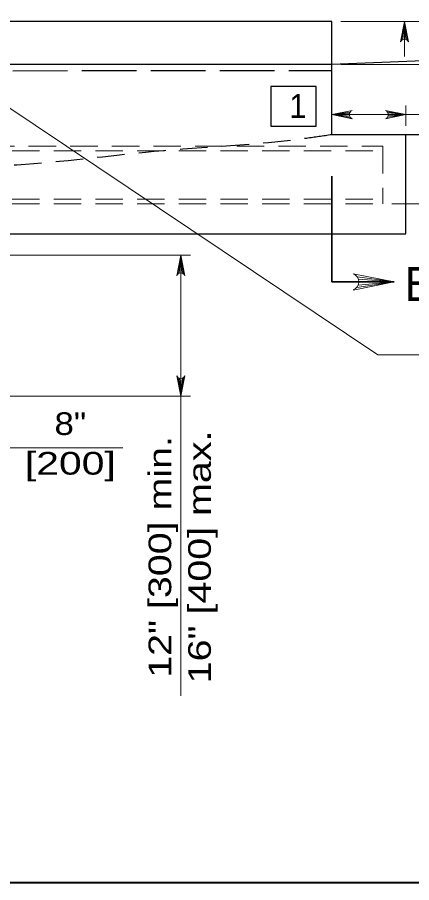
# Model space of a CAD drawing. Extents: x -1431.2 to -1397.2, y -1045.1 to -1001.1.
# Drawn here: x -1417.19 to -1414.42, y -1022.58 to -1016.52 of the extents above; entities that cross this region are included whole.
import ezdxf
from ezdxf.enums import TextEntityAlignment as Align

# ---------------------------------------------------------------- set-up
doc = ezdxf.new("R2010")
doc.units = 0
doc.header["$LTSCALE"] = 0.064
doc.linetypes.add('LONG_DASHED', pattern=[7.5, 6, -1.5])
doc.linetypes.add('MEDIUM_DASHED', pattern=[4.5, 3, -1.5])
doc.layers.add('1', color=7, linetype='Continuous', lineweight=13)

msp = doc.modelspace()

# ---------------------------------------------------------------- linework, layer by layer
at = {"layer": '1'}
for p, q in [((-1414.922, -1016.54658), (-1413.9755, -1016.54658)), ((-1414.49525, -1016.6775), (-1414.47525, -1016.54658)), ((-1414.48683, -1016.67258), (-1414.47525, -1016.54658)), ((-1414.47525, -1016.79125), (-1414.47525, -1016.54658)), ((-1414.47525, -1016.67025), (-1414.47525, -1016.54658)), ((-1414.46608, -1016.67158), (-1414.47525, -1016.54658)), ((-1414.45717, -1016.676), (-1414.47525, -1016.54658)), ((-1414.922, -1016.84758), (-1411.48458, -1016.84758)), ((-1414.59558, -1017.17883), (-1414.46475, -1017.19883)), ((-1414.46475, -1017.27683), (-1414.46475, -1017.13575)), ((-1414.85567, -1017.18067), (-1414.98508, -1017.19883)), ((-1414.86008, -1017.18967), (-1414.98508, -1017.19883)), ((-1414.98508, -1017.19883), (-1413.19358, -1017.19883)), ((-1414.86142, -1017.19883), (-1414.98508, -1017.19883)), ((-1414.85908, -1017.21042), (-1414.98508, -1017.19883)), ((-1414.85417, -1017.21883), (-1414.98508, -1017.19883)), ((-1414.59408, -1017.21692), (-1414.46475, -1017.19883)), ((-1414.59067, -1017.18717), (-1414.46475, -1017.19883)), ((-1414.58967, -1017.20792), (-1414.46475, -1017.19883)), ((-1414.58833, -1017.19883), (-1414.46475, -1017.19883)), ((-1414.922, -1017.33992), (-1412.21383, -1017.33992)), ((-1414.563, -1017.824), (-1412.22208, -1017.824)), ((-1417.76217, -1018.18442), (-1415.97617, -1018.18442)), ((-1416.0635, -1018.31525), (-1416.0435, -1018.18442)), ((-1416.05508, -1018.31033), (-1416.0435, -1018.18442)), ((-1416.0435, -1021.27142), (-1416.0435, -1018.18442)), ((-1416.0435, -1018.308), (-1416.0435, -1018.18442)), ((-1416.03433, -1018.30933), (-1416.0435, -1018.18442)), ((-1416.02542, -1018.31375), (-1416.0435, -1018.18442)), ((-1414.81025, -1018.4105), (-1414.54842, -1018.3705)), ((-1414.80717, -1018.33425), (-1414.54842, -1018.3705)), ((-1414.80033, -1018.39375), (-1414.54842, -1018.3705)), ((-1414.79842, -1018.35217), (-1414.54842, -1018.3705)), ((-1414.79575, -1018.3705), (-1414.54842, -1018.3705)), ((-1416.06158, -1019.0415), (-1416.0435, -1019.17083)), ((-1416.05267, -1019.04592), (-1416.0435, -1019.17083)), ((-1416.0235, -1019.04), (-1416.0435, -1019.17083)), ((-1416.03192, -1019.04492), (-1416.0435, -1019.17083)), ((-1416.0435, -1019.04725), (-1416.0435, -1019.17083)), ((-1417.775, -1019.17083), (-1415.97617, -1019.17083)), ((-1417.79208, -1019.53367), (-1416.45075, -1019.53367))]:
    msp.add_line(p, q, dxfattribs=at)
at = {"layer": '1', "lineweight": 25}
for p, q in [((-1411.525, -1016.71175), (-1414.98508, -1016.84758)), ((-1414.98508, -1016.84758), (-1417.70592, -1016.84758)), ((-1414.46475, -1018.03408), (-1414.46475, -1017.33992)), ((-1417.26308, -1018.03408), (-1414.46475, -1018.03408))]:
    msp.add_line(p, q, dxfattribs=at)
at = {"layer": '1', "linetype": 'LONG_DASHED', "lineweight": 25}
msp.add_line((-1417.70592, -1016.89183), (-1414.98508, -1016.88942), dxfattribs=at)
at = {"layer": '1', "linetype": 'MEDIUM_DASHED'}
for p, q in [((-1414.62608, -1017.42058), (-1414.62608, -1017.824)), ((-1423.35717, -1017.45292), (-1414.62608, -1017.45292)), ((-1423.35717, -1017.79175), (-1414.62608, -1017.79175)), ((-1423.35717, -1017.824), (-1414.62608, -1017.824))]:
    msp.add_line(p, q, dxfattribs=at)
at = {"layer": '1', "lineweight": 35}
for p in [(-1414.98508, -1017.63067), (-1414.54842, -1018.3705)]:
    msp.add_line(p, (-1414.98508, -1018.3705), dxfattribs=at)
at = {"layer": '1', "lineweight": 25}
for points in [[(-1397.74575, -1022.57983), (-1429.24575, -1022.57983), (-1429.24575, -1001.57983)], [(-1414.98508, -1017.33992), (-1414.98508, -1016.54658), (-1422.97483, -1016.54658)], [(-1410.98275, -1017.33992), (-1411.01725, -1017.33992), (-1414.98508, -1017.33992)]]:
    msp.add_lwpolyline(points, dxfattribs=at)
at = {"layer": '1', "lineweight": 40}
msp.add_lwpolyline([(-1429.24575, -1001.57983), (-1397.74575, -1001.57983), (-1397.74575, -1022.57983), (-1429.24575, -1022.57983)], close=True, dxfattribs=at)
at = {"layer": '1'}
for points in [[(-1414.50383, -1016.6895), (-1414.47525, -1016.54658), (-1414.44667, -1016.6895)], [(-1417.50675, -1016.97758), (-1414.66083, -1018.88217), (-1414.36975, -1018.88217)], [(-1414.84217, -1017.22742), (-1414.98508, -1017.19883), (-1414.84217, -1017.17025)], [(-1414.60758, -1017.17025), (-1414.46475, -1017.19883), (-1414.60758, -1017.22742)], [(-1416.07208, -1018.32725), (-1416.0435, -1018.18442), (-1416.01492, -1018.32725)], [(-1414.83425, -1018.42767), (-1414.54842, -1018.3705), (-1414.83425, -1018.31333)], [(-1416.01492, -1019.028), (-1416.0435, -1019.17083), (-1416.07208, -1019.028)]]:
    msp.add_lwpolyline(points, dxfattribs=at)
at = {"layer": '1', "lineweight": 25}
msp.add_lwpolyline([(-1415.41133, -1017.00258), (-1415.41133, -1017.28042), (-1415.09408, -1017.28042), (-1415.09408, -1017.00258)], close=True, dxfattribs=at)
at = {"layer": '1', "linetype": 'MEDIUM_DASHED'}
msp.add_lwpolyline([(-1423.35717, -1017.42058), (-1421.19792, -1017.42058), (-1414.62608, -1017.42058)], dxfattribs=at)
at = {"layer": '1'}
for centre, radius, start, end in [((-1414.4752, -1016.70105), 0.03084, 22.08782, 157.91395), ((-1414.83062, -1017.19877), 0.03084, 112.08782, 247.91395), ((-1414.61916, -1017.19883), 0.03084, 292.08782, 67.91395), ((-1416.04347, -1018.33882), 0.03084, 22.08782, 157.91395), ((-1414.8573, -1018.37041), 0.06168, 292.08605, 67.91218), ((-1416.04353, -1019.01644), 0.03084, 202.08782, 337.91395)]:
    msp.add_arc(centre, radius, start, end, dxfattribs=at)
at = {"layer": '1', "linetype": 'MEDIUM_DASHED', "lineweight": 25}
msp.add_spline([(-1414.98508, -1017.33992), (-1415.16275, -1017.36567), (-1416.231, -1017.45842), (-1417.192, -1017.55267), (-1417.6565, -1017.60142), (-1417.70483, -1017.62067), (-1417.73017, -1017.6525), (-1417.75708, -1017.69033), (-1417.79225, -1017.742)], degree=3, dxfattribs=at)

# ---------------------------------------------------------------- texts
at = {"layer": '1', "width": 0.95}
for s, height, p in [('1', 0.1682, (-1415.28158, -1017.222)), ('B', 0.2382, (-1414.47317, -1018.50417))]:
    msp.add_text(s, height=height, dxfattribs=at).set_placement(p)
at = {"layer": '1'}
for s, width, p in [('8"', 1.15, (-1416.81758, -1019.44325)), ('[200]', 1.35, (-1416.81762, -1019.72108))]:
    msp.add_text(s, height=0.1588, dxfattribs=dict(at, width=width)).set_placement(p, align=Align.CENTER)
at = {"layer": '1', "width": 1.3}
for s, p in [('12" [300] min.', (-1416.11033, -1020.29754)), ('16" [400] max.', (-1415.8325, -1020.29758))]:
    msp.add_text(s, height=0.1588, rotation=90, dxfattribs=at).set_placement(p, align=Align.CENTER)

doc.saveas('drawing.dxf')
